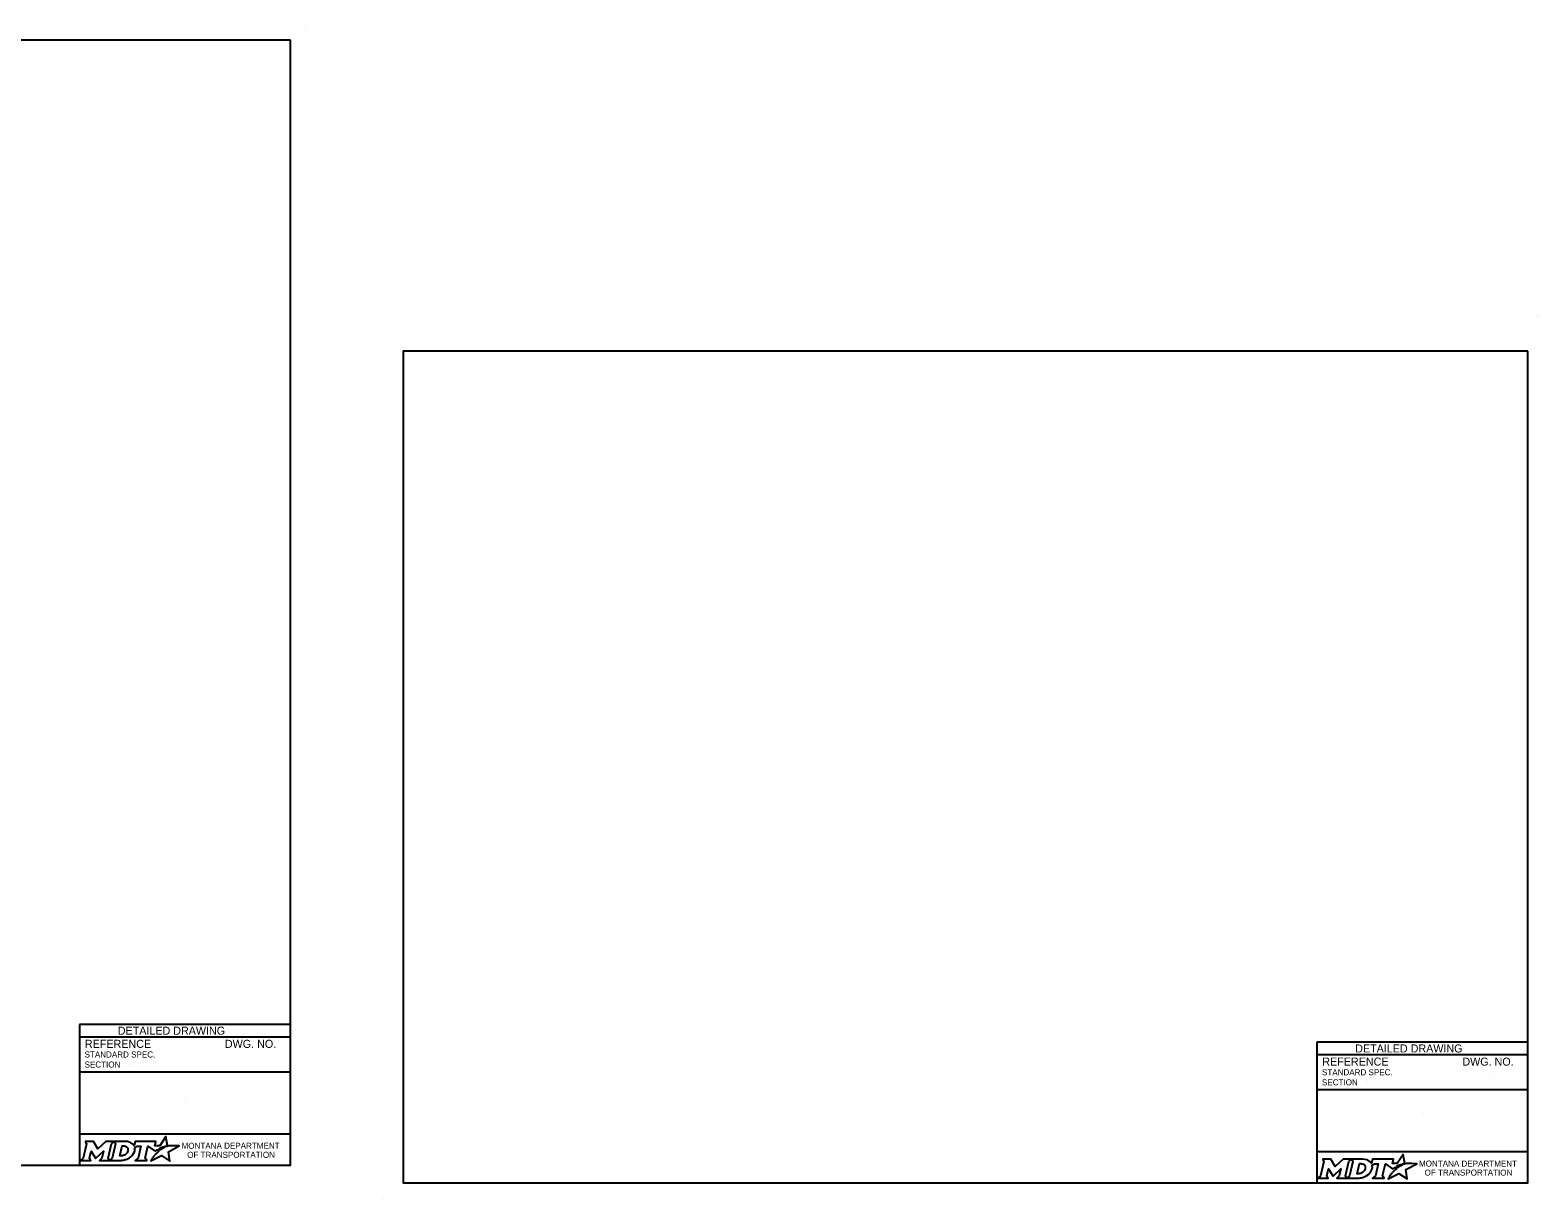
# Model space of a CAD drawing. Extents: x 49991.4 to 50021, y 49987.6 to 50011.4.
# Drawn here: x 50006.02 to 50021.04, y 49999.74 to 50011.36 of the extents above; entities that cross this region are included whole.
import ezdxf

# ---------------------------------------------------------------- set-up
doc = ezdxf.new("R2010")
doc.units = 0
for name, color, linetype in [('Default', 7, 'Continuous'), ('Level 1', 7, 'Continuous'), ('Level 2', 7, 'Continuous'), ('Level 4', 7, 'Continuous')]:
    doc.layers.add(name, color=color, linetype=linetype)

msp = doc.modelspace()

# ---------------------------------------------------------------- linework, layer by layer
at = {"layer": 'Default'}
for points in [[(50018.893, 50000.121), (50018.907, 50000.097), (50018.874, 49999.954), (50018.848, 49999.931), (50018.95, 49999.931), (50018.936, 49999.954), (50018.952, 50000.024), (50018.996, 49999.955), (50019.002, 49999.955), (50019.077, 50000.025), (50019.06, 49999.954), (50019.035, 49999.932), (50019.137, 49999.932), (50019.123, 49999.955), (50019.156, 50000.097)], [(50019.156, 50000.097), (50019.182, 50000.121), (50019.099, 50000.121), (50019.02, 50000.048), (50018.975, 50000.12), (50018.893, 50000.121)], [(50019.295, 50000.121), (50019.182, 50000.121), (50019.196, 50000.098), (50019.163, 49999.954), (50019.137, 49999.932), (50019.248, 49999.932)], [(50019.319, 50000.034), (50019.318, 50000.026), (50019.315, 50000.017), (50019.311, 50000.008), (50019.305, 50000.001), (50019.299, 49999.994), (50019.291, 49999.988), (50019.282, 49999.983), (50019.273, 49999.979), (50019.264, 49999.977), (50019.255, 49999.976), (50019.239, 49999.976), (50019.263, 50000.076), (50019.279, 50000.076), (50019.286, 50000.075), (50019.294, 50000.073), (50019.301, 50000.07), (50019.307, 50000.066), (50019.311, 50000.061), (50019.315, 50000.055), (50019.318, 50000.049), (50019.319, 50000.042), (50019.32, 50000.038), (50019.319, 50000.034)], [(50019.7, 50000.068), (50019.69, 50000.074), (50019.702, 50000.076), (50019.713, 50000.078), (50019.696, 50000.168), (50019.636, 50000.077), (50019.589, 50000.076), (50019.599, 50000.12), (50019.39, 50000.121), (50019.38, 50000.078), (50019.374, 50000.086)], [(50019.387, 50000.062), (50019.411, 50000.075), (50019.448, 50000.075), (50019.42, 49999.954), (50019.392, 49999.931), (50019.508, 49999.931), (50019.491, 49999.954), (50019.52, 50000.075), (50019.591, 50000.023), (50019.612, 50000.038), (50019.632, 50000.027)], [(50019.576, 49999.971), (50019.561, 49999.947), (50019.556, 49999.939), (50019.55, 49999.931), (50019.548, 49999.926), (50019.653, 49999.979), (50019.737, 49999.924), (50019.724, 50000.017), (50019.831, 50000.075), (50019.782, 50000.076), (50019.751, 50000.077), (50019.731, 50000.077), (50019.724, 50000.075), (50019.719, 50000.074), (50019.711, 50000.072), (50019.7, 50000.068)], [(50019.293, 49999.939), (50019.302, 49999.942), (50019.315, 49999.947), (50019.335, 49999.958)], [(50019.59, 49999.987), (50019.59, 49999.987)], [(50019.65, 50000.04), (50019.648, 50000.039), (50019.629, 50000.048), (50019.639, 50000.054), (50019.644, 50000.056), (50019.652, 50000.06), (50019.658, 50000.063), (50019.666, 50000.066), (50019.673, 50000.068), (50019.685, 50000.061), (50019.681, 50000.059), (50019.676, 50000.056), (50019.672, 50000.054), (50019.667, 50000.051), (50019.665, 50000.05), (50019.662, 50000.049), (50019.66, 50000.047), (50019.658, 50000.046), (50019.655, 50000.044), (50019.652, 50000.042), (50019.65, 50000.04)]]:
    msp.add_lwpolyline(points, dxfattribs=at)
for centre, radius, start, end in [((50019.274, 50000.059), 0.118, 300.9103, 339.1383), ((50019.319, 50000.042), 0.0709, 339.5329, 15.8582)]:
    msp.add_arc(centre, radius, start, end, dxfattribs=at)
for centre, major_axis, ratio, start_param, end_param in [((50019.293, 50000.073), (0.0834, -0.0037), 0.568097, 0.61298, 1.570796), ((50019.349, 50000.081), (0.0361, -0.0295), 0.469099, 1.225588, 1.570796), ((50019.248, 50000.08), (0, 0.148), 0.987302, 3.139398, 3.456847), ((50019.583, 49999.979), (-0.00694, -0.00806), 0.008222, 0, 3.137361), ((50019.6, 49999.997), (-0.0098, -0.0102), 0.016458, 3.141593, 6.279097), ((50019.621, 50000.017), (-0.0112, -0.0097), 0.021651, 3.157348, 6.283185)]:
    msp.add_ellipse(centre, major_axis=major_axis, ratio=ratio, start_param=start_param, end_param=end_param, dxfattribs=at)
at = {"layer": 'Level 1'}
for p, q in [((50008.765, 50011.363), (50008.765, 50011.363)), ((50021.038, 50008.524), (50021.038, 50008.524)), ((50009.537, 49999.736), (50009.537, 49999.736))]:
    msp.add_line(p, q, dxfattribs=at)
for points in [[(50008.615, 50011.263), (50000.336, 50011.263), (50000.336, 50000.062), (50008.615, 50000.062)], [(50020.938, 50008.165), (50009.737, 50008.165), (50009.737, 49999.886), (50020.938, 49999.886)]]:
    msp.add_lwpolyline(points, close=True, dxfattribs=at)
at = {"layer": 'Level 2'}
for p, q in [((50008.615, 50001.462), (50006.515, 50001.462)), ((50006.515, 50001.462), (50006.515, 50000.062)), ((50008.615, 50001.337), (50006.515, 50001.337)), ((50008.615, 50000.987), (50006.515, 50000.987)), ((50007.009, 50001.063), (50007.009, 50001.063)), ((50008.251, 50001.122), (50008.251, 50001.122)), ((50007.565, 50000.738), (50007.565, 50000.738)), ((50008.615, 50000.369), (50006.515, 50000.369))]:
    msp.add_line(p, q, dxfattribs=at)
for points in [[(50006.57, 50000.297), (50006.584, 50000.274), (50006.551, 50000.131), (50006.525, 50000.108), (50006.627, 50000.108), (50006.613, 50000.131), (50006.629, 50000.201), (50006.673, 50000.132), (50006.678, 50000.132), (50006.753, 50000.202), (50006.737, 50000.13), (50006.712, 50000.108), (50006.814, 50000.108), (50006.8, 50000.132), (50006.833, 50000.274)], [(50006.833, 50000.274), (50006.859, 50000.297), (50006.776, 50000.297), (50006.697, 50000.224), (50006.652, 50000.297), (50006.57, 50000.297)], [(50006.972, 50000.297), (50006.859, 50000.297), (50006.873, 50000.275), (50006.839, 50000.131), (50006.814, 50000.108), (50006.925, 50000.108)], [(50006.996, 50000.211), (50006.995, 50000.203), (50006.992, 50000.193), (50006.988, 50000.185), (50006.982, 50000.178), (50006.976, 50000.171), (50006.968, 50000.164), (50006.959, 50000.16), (50006.95, 50000.156), (50006.941, 50000.154), (50006.932, 50000.153), (50006.916, 50000.153), (50006.94, 50000.253), (50006.956, 50000.253), (50006.963, 50000.252), (50006.971, 50000.25), (50006.977, 50000.247), (50006.983, 50000.243), (50006.988, 50000.238), (50006.992, 50000.232), (50006.995, 50000.226), (50006.996, 50000.218), (50006.996, 50000.215), (50006.996, 50000.211)], [(50007.377, 50000.245), (50007.367, 50000.25), (50007.378, 50000.253), (50007.39, 50000.255), (50007.373, 50000.345), (50007.313, 50000.254), (50007.266, 50000.253), (50007.276, 50000.297), (50007.067, 50000.297), (50007.057, 50000.255), (50007.051, 50000.263)], [(50007.064, 50000.238), (50007.088, 50000.251), (50007.125, 50000.251), (50007.097, 50000.131), (50007.069, 50000.108), (50007.185, 50000.108), (50007.168, 50000.131), (50007.196, 50000.251), (50007.268, 50000.2), (50007.289, 50000.215), (50007.309, 50000.204)], [(50007.253, 50000.148), (50007.237, 50000.124), (50007.233, 50000.116), (50007.227, 50000.107), (50007.225, 50000.103), (50007.33, 50000.156), (50007.414, 50000.101), (50007.401, 50000.194), (50007.508, 50000.252), (50007.458, 50000.253), (50007.428, 50000.253), (50007.407, 50000.254), (50007.401, 50000.252), (50007.396, 50000.251), (50007.387, 50000.249), (50007.377, 50000.245)], [(50007.327, 50000.217), (50007.324, 50000.215), (50007.306, 50000.225), (50007.316, 50000.231), (50007.32, 50000.233), (50007.329, 50000.237), (50007.335, 50000.239), (50007.343, 50000.243), (50007.35, 50000.245), (50007.362, 50000.238), (50007.358, 50000.236), (50007.353, 50000.233), (50007.349, 50000.231), (50007.344, 50000.228), (50007.342, 50000.227), (50007.339, 50000.225), (50007.337, 50000.224), (50007.334, 50000.222), (50007.332, 50000.221), (50007.329, 50000.219), (50007.327, 50000.217)], [(50006.97, 50000.116), (50006.979, 50000.118), (50006.992, 50000.124), (50007.012, 50000.135)], [(50007.267, 50000.164), (50007.267, 50000.164)]]:
    msp.add_lwpolyline(points, dxfattribs=at)
for centre, radius, start, end in [((50006.995, 50000.219), 0.0709, 339.5329, 15.8582), ((50006.951, 50000.236), 0.118, 300.9103, 339.1383)]:
    msp.add_arc(centre, radius, start, end, dxfattribs=at)
for centre, major_axis, ratio, start_param, end_param in [((50006.97, 50000.25), (0.0834, -0.0037), 0.568097, 0.61298, 1.570796), ((50007.026, 50000.257), (0.0361, -0.0295), 0.469099, 1.225588, 1.570796), ((50006.925, 50000.257), (0, 0.148), 0.987302, 3.139398, 3.456847), ((50007.26, 50000.156), (-0.00694, -0.00806), 0.008222, 0, 3.137361), ((50007.276, 50000.174), (-0.0098, -0.0102), 0.016458, 3.141593, 6.279097), ((50007.297, 50000.194), (-0.0112, -0.0097), 0.021651, 3.157348, 6.283185)]:
    msp.add_ellipse(centre, major_axis=major_axis, ratio=ratio, start_param=start_param, end_param=end_param, dxfattribs=at)
at = {"layer": 'Level 4'}
for p, q in [((50020.938, 50001.286), (50018.838, 50001.286)), ((50018.838, 50001.286), (50018.838, 49999.886)), ((50020.938, 50001.161), (50018.838, 50001.161)), ((50019.332, 50000.886), (50019.332, 50000.886)), ((50020.574, 50000.946), (50020.574, 50000.946)), ((50020.938, 50000.811), (50018.838, 50000.811)), ((50019.888, 50000.562), (50019.888, 50000.562)), ((50020.938, 50000.193), (50018.838, 50000.193))]:
    msp.add_line(p, q, dxfattribs=at)

# ---------------------------------------------------------------- texts
at = {"layer": 'Default'}
for s, p in [('MONTANA DEPARTMENT', (50019.854, 50000.047)), ('OF TRANSPORTATION', (50019.91, 49999.957))]:
    msp.add_text(s, height=0.06, dxfattribs=at).set_placement(p)
at = {"layer": 'Level 2'}
for s, height, p in [('DETAILED DRAWING', 0.0799, (50006.896, 50001.36)), ('REFERENCE', 0.08, (50006.568, 50001.229)), ('DWG. NO.', 0.08, (50007.962, 50001.229)), ('STANDARD SPEC.', 0.06, (50006.565, 50001.133)), ('SECTION', 0.06, (50006.565, 50001.033)), ('MONTANA DEPARTMENT', 0.06, (50007.531, 50000.224)), ('OF TRANSPORTATION', 0.06, (50007.587, 50000.134))]:
    msp.add_text(s, height=height, dxfattribs=at).set_placement(p)
at = {"layer": 'Level 4'}
for s, height, p in [('REFERENCE', 0.08, (50018.891, 50001.052)), ('DETAILED DRAWING', 0.0799, (50019.219, 50001.183)), ('DWG. NO.', 0.08, (50020.286, 50001.052)), ('STANDARD SPEC.', 0.06, (50018.888, 50000.956)), ('SECTION', 0.06, (50018.888, 50000.856))]:
    msp.add_text(s, height=height, dxfattribs=at).set_placement(p)

doc.saveas('drawing.dxf')
